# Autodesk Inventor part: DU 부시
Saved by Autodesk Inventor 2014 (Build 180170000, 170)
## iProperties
Created: 2026-09
Part Number: DU 부시
Material: 일반
Document SubType Name: Modeling
Designer: dg
Density: 1 g/cm^3
Appearance: 기본값
Author: dg
Author: jhkim
Creation Date: 2026-08-26
Sending System: Autodesk Inventor 2027
Preprocessor: ST-DEVELOPER v20.1
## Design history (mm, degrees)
node "DU 부시1"
node "솔리드1"
node "기준1"
